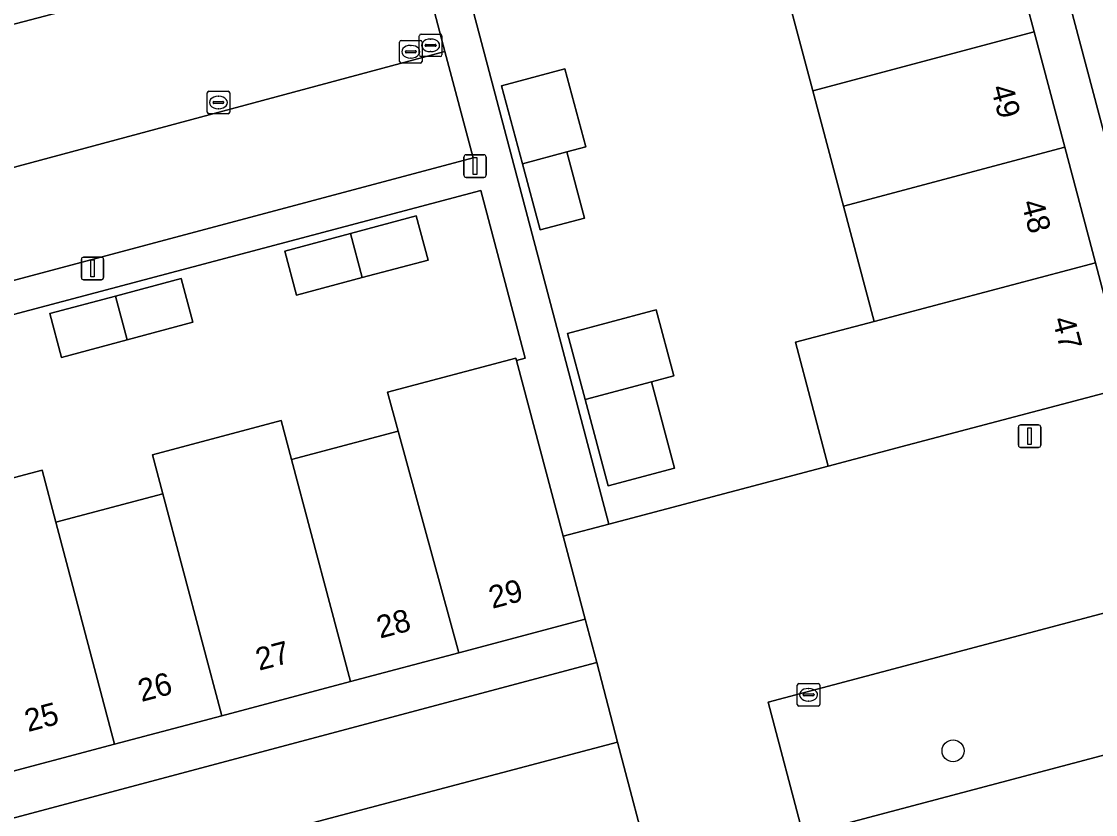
# Model space of a CAD drawing. Extents: x 162542 to 163147, y 380779 to 381521.
# Drawn here: x 162709.87 to 162757.53, y 381197.72 to 381232.91 of the extents above; entities that cross this region are included whole.
import ezdxf

# ---------------------------------------------------------------- set-up
doc = ezdxf.new("R2010")
doc.units = 0
for name, color, linetype in [('IMGEO_Boom', 7, 'Continuous'), ('IMGEO_Erf', 7, 'Continuous'), ('IMGEO_Groenvoorziening', 7, 'Continuous'), ('IMGEO_Kolk', 7, 'Continuous'), ('IMGEO_Lichtmast', 7, 'Continuous'), ('IMGEO_Pand', 7, 'Continuous'), ('IMGEO_Pand_nummerreeks', 7, 'Continuous'), ('IMGEO_Parkeervlak_open', 7, 'Continuous'), ('IMGEO_Rijbaan_lokaal_open', 7, 'Continuous'), ('IMGEO_Rioolput', 7, 'Continuous'), ('IMGEO_Voetpad_open', 7, 'Continuous')]:
    doc.layers.add(name, color=color, linetype=linetype)

msp = doc.modelspace()

# ---------------------------------------------------------------- linework, layer by layer
at = {"layer": 'IMGEO_Boom'}
msp.add_circle((162751.21, 381200.544), 0.489, dxfattribs=at)
at = {"layer": 'IMGEO_Erf'}
for points in [[(162744.149, 381279.784), (162742.367, 381279.309), (162743.667, 381274.41), (162743.797, 381273.921), (162742.727, 381273.637), (162743.189, 381271.897), (162744.259, 381272.181), (162745.094, 381269.035), (162746.512, 381263.696), (162747.763, 381258.981), (162749.288, 381253.236), (162750.533, 381248.547), (162751.429, 381245.173), (162750.365, 381244.868), (162750.827, 381243.126), (162751.891, 381243.431), (162751.943, 381243.235), (162752.106, 381242.624), (162753.452, 381237.55), (162754.805, 381232.452), (162756.164, 381227.332), (162757.525, 381222.201), (162758.984, 381216.704), (162760.777, 381217.178)], [(162733.985, 381230.811), (162734.91, 381227.345), (162734.066, 381227.12), (162734.849, 381224.188), (162732.878, 381223.662), (162732.095, 381226.594), (162731.17, 381230.06)], [(162721.556, 381222.72), (162724.468, 381223.499), (162727.387, 381224.28), (162727.911, 381222.324), (162724.992, 381221.543), (162722.072, 381220.761)], [(162711.121, 381219.944), (162714.034, 381220.723), (162716.95, 381221.503), (162717.469, 381219.561), (162714.552, 381218.783), (162711.635, 381218.004)], [(162737.855, 381220.069), (162738.035, 381220.117), (162738.819, 381217.18), (162737.828, 381216.916), (162738.845, 381213.083), (162735.907, 381212.3), (162734.886, 381216.132), (162734.103, 381219.069)]]:
    msp.add_lwpolyline(points, close=True, dxfattribs=at)
for points in [[(162721.568, 381264.953), (162735.925, 381210.607), (162745.669, 381213.183), (162744.216, 381218.679), (162747.704, 381219.602), (162746.343, 381224.72), (162744.981, 381229.839), (162743.62, 381234.957)], [(162705.078, 381211.488), (162710.779, 381213.004), (162711.391, 381210.689), (162716.137, 381211.949), (162715.678, 381213.677), (162721.392, 381215.196), (162721.852, 381213.468), (162726.586, 381214.725), (162726.113, 381216.459), (162731.811, 381217.971), (162731.839, 381217.865), (162732.225, 381217.967), (162730.249, 381225.411), (162696.73, 381216.515)], [(162690.946, 381195.54), (162687.929, 381198.743), (162687.849, 381198.668), (162687.41, 381199.136), (162687.487, 381199.208), (162684.47, 381202.415), (162684.391, 381202.339), (162683.889, 381202.869), (162682.507, 381201.562), (162690.949, 381192.615), (162735.396, 381204.465), (162734.886, 381206.386), (162729.268, 381204.894), (162724.473, 381203.621), (162718.757, 381202.103), (162713.994, 381200.841), (162708.31, 381199.334), (162703.321, 381198.012), (162703.349, 381197.905), (162703.116, 381197.844), (162702.845, 381197.772), (162702.817, 381197.878), (162702.689, 381197.844), (162699.57, 381197.013)]]:
    msp.add_lwpolyline(points, dxfattribs=at)
at = {"layer": 'IMGEO_Groenvoorziening'}
for points in [[(162725.799, 381242.395), (162724.166, 381248.556), (162706.988, 381232.279), (162707.019, 381232.142), (162707.144, 381232.175), (162717.44, 381234.879), (162717.359, 381235.188), (162716.135, 381239.802)], [(162763.302, 381208.084), (162743.002, 381202.706), (162744.562, 381196.817), (162764.861, 381202.201)], [(162736.313, 381200.934), (162717.693, 381196.001), (162719.198, 381190.095), (162737.873, 381195.045)]]:
    msp.add_lwpolyline(points, close=True, dxfattribs=at)
at = {"layer": 'IMGEO_Kolk'}
for p, q in [((162726.643, 381231.14), (162726.643, 381231.992)), ((162726.718, 381232.066), (162727.57, 381232.066)), ((162727.131, 381231.846), (162727.156, 381231.846)), ((162727.644, 381231.992), (162727.644, 381231.14)), ((162726.902, 381231.56), (162726.902, 381231.572)), ((162727.34, 381231.523), (162726.942, 381231.523)), ((162726.945, 381231.609), (162727.343, 381231.609)), ((162727.154, 381231.286), (162727.129, 381231.286)), ((162727.386, 381231.572), (162727.386, 381231.56)), ((162727.57, 381231.066), (162726.718, 381231.066)), ((162718.106, 381228.888), (162718.106, 381229.74)), ((162718.181, 381229.814), (162719.033, 381229.814)), ((162718.594, 381229.594), (162718.619, 381229.594)), ((162719.107, 381229.74), (162719.107, 381228.888)), ((162718.365, 381229.308), (162718.365, 381229.32)), ((162718.803, 381229.271), (162718.405, 381229.271)), ((162718.408, 381229.357), (162718.806, 381229.357)), ((162718.617, 381229.034), (162718.592, 381229.034)), ((162718.849, 381229.32), (162718.849, 381229.308)), ((162719.033, 381228.814), (162718.181, 381228.814))]:
    msp.add_line(p, q, dxfattribs=at)
for points in [[(162726.643, 381231.14), (162726.643, 381231.992)], [(162726.718, 381232.066), (162727.57, 381232.066)], [(162727.644, 381231.992), (162727.644, 381231.14)], [(162727.57, 381231.066), (162726.718, 381231.066)], [(162718.106, 381228.888), (162718.106, 381229.74)], [(162718.181, 381229.814), (162719.033, 381229.814)], [(162719.107, 381229.74), (162719.107, 381228.888)], [(162719.033, 381228.814), (162718.181, 381228.814)]]:
    msp.add_lwpolyline(points, dxfattribs=at)
for centre, radius, start, end in [((162726.72, 381231.99), 0.0765, 91.552, 178.448), ((162726.72, 381231.99), 0.0765, 91.552, 178.448), ((162727.568, 381231.99), 0.0765, 1.552, 88.448), ((162727.568, 381231.99), 0.0765, 1.552, 88.448), ((162726.942, 381231.569), 0.0403, 85.8775, 175.7526), ((162726.939, 381231.559), 0.0366, 178.938, 274.7102), ((162727.343, 381231.566), 0.043, 264.8664, 352.4533), ((162727.347, 381231.571), 0.0386, 1.7309, 96.639), ((162726.72, 381231.142), 0.0765, 181.552, 268.448), ((162726.72, 381231.142), 0.0765, 181.552, 268.448), ((162727.568, 381231.142), 0.0765, 271.552, 358.448), ((162727.568, 381231.142), 0.0765, 271.552, 358.448), ((162718.183, 381229.738), 0.0765, 91.552, 178.448), ((162718.183, 381229.738), 0.0765, 91.552, 178.448), ((162719.031, 381229.738), 0.0765, 1.552, 88.448), ((162719.031, 381229.738), 0.0765, 1.552, 88.448), ((162718.405, 381229.317), 0.0403, 85.8775, 175.7526), ((162718.402, 381229.307), 0.0366, 178.938, 274.7102), ((162718.806, 381229.314), 0.043, 264.8664, 352.4533), ((162718.81, 381229.319), 0.0386, 1.7309, 96.639), ((162718.183, 381228.89), 0.0765, 181.552, 268.448), ((162718.183, 381228.89), 0.0765, 181.552, 268.448), ((162719.031, 381228.89), 0.0765, 271.552, 358.448), ((162719.031, 381228.89), 0.0765, 271.552, 358.448)]:
    msp.add_arc(centre, radius, start, end, dxfattribs=at)
for centre, major_axis, ratio, start_param, end_param in [((162727.13, 381231.566), (-0.387, 0.002), 0.722429, 4.712389, 7.853982), ((162727.155, 381231.566), (-0.39, 0.002), 0.717154, 1.570796, 4.712389), ((162718.593, 381229.314), (-0.387, 0.002), 0.722429, 4.712389, 7.853982), ((162718.618, 381229.314), (-0.39, 0.002), 0.717154, 1.570796, 4.712389)]:
    msp.add_ellipse(centre, major_axis=major_axis, ratio=ratio, start_param=start_param, end_param=end_param, dxfattribs=at)
at = {"layer": 'IMGEO_Lichtmast'}
for p, q in [((162729.597, 381226.993), (162730.387, 381226.993)), ((162730.387, 381226.993), (162729.597, 381226.993)), ((162729.497, 381226.093), (162729.497, 381226.893)), ((162729.497, 381226.893), (162729.497, 381226.093)), ((162730.487, 381226.893), (162730.487, 381226.093)), ((162730.487, 381226.093), (162730.487, 381226.893)), ((162730.387, 381225.993), (162729.597, 381225.993)), ((162729.597, 381225.993), (162730.387, 381225.993)), ((162712.522, 381221.551), (162712.522, 381222.351)), ((162712.522, 381222.351), (162712.522, 381221.551)), ((162712.622, 381222.451), (162713.412, 381222.451)), ((162713.412, 381222.451), (162712.622, 381222.451)), ((162713.512, 381222.351), (162713.512, 381221.551)), ((162713.512, 381221.551), (162713.512, 381222.351)), ((162713.412, 381221.451), (162712.622, 381221.451)), ((162712.622, 381221.451), (162713.412, 381221.451)), ((162754.107, 381214.109), (162754.107, 381214.909)), ((162754.107, 381214.909), (162754.107, 381214.109)), ((162754.207, 381215.009), (162754.997, 381215.009)), ((162754.997, 381215.009), (162754.207, 381215.009)), ((162755.097, 381214.909), (162755.097, 381214.109)), ((162755.097, 381214.109), (162755.097, 381214.909)), ((162754.997, 381214.009), (162754.207, 381214.009)), ((162754.207, 381214.009), (162754.997, 381214.009))]:
    msp.add_line(p, q, dxfattribs=at)
for points in [[(162729.917, 381226.868), (162730.067, 381226.868), (162730.067, 381226.118), (162729.917, 381226.118), (162729.917, 381226.868)], [(162712.942, 381222.326), (162713.092, 381222.326), (162713.092, 381221.576), (162712.942, 381221.576), (162712.942, 381222.326)], [(162754.527, 381214.884), (162754.677, 381214.884), (162754.677, 381214.134), (162754.527, 381214.134), (162754.527, 381214.884)]]:
    msp.add_lwpolyline(points, dxfattribs=at)
for centre, start, end in [((162729.597, 381226.893), 90, 180), ((162729.597, 381226.893), 90, 180), ((162730.387, 381226.893), 0, 90), ((162730.387, 381226.893), 360, 90), ((162729.597, 381226.093), 180, 270), ((162729.597, 381226.093), 180, 270), ((162730.387, 381226.093), 270, 0), ((162730.387, 381226.093), 270, 0), ((162712.622, 381222.351), 90, 180), ((162712.622, 381222.351), 90, 180), ((162713.412, 381222.351), 0, 90), ((162713.412, 381222.351), 360, 90), ((162712.622, 381221.551), 180, 270), ((162712.622, 381221.551), 180, 270), ((162713.412, 381221.551), 270, 0), ((162713.412, 381221.551), 270, 0), ((162754.207, 381214.909), 90, 180), ((162754.207, 381214.909), 90, 180), ((162754.997, 381214.909), 0, 90), ((162754.997, 381214.909), 360, 90), ((162754.207, 381214.109), 180, 270), ((162754.207, 381214.109), 180, 270), ((162754.997, 381214.109), 270, 0), ((162754.997, 381214.109), 270, 0)]:
    msp.add_arc(centre, 0.1, start, end, dxfattribs=at)
at = {"layer": 'IMGEO_Pand'}
for points in [[(162753.452, 381237.55), (162743.62, 381234.957), (162744.981, 381229.839), (162754.805, 381232.452)], [(162754.805, 381232.452), (162744.981, 381229.839), (162746.343, 381224.72), (162756.164, 381227.332)], [(162733.985, 381230.811), (162731.17, 381230.06), (162732.095, 381226.594), (162734.066, 381227.12), (162734.91, 381227.345)], [(162734.066, 381227.12), (162732.095, 381226.594), (162732.878, 381223.662), (162734.849, 381224.188)], [(162757.525, 381222.201), (162756.164, 381227.332), (162746.343, 381224.72), (162747.704, 381219.602)], [(162727.387, 381224.28), (162724.468, 381223.499), (162724.992, 381221.543), (162727.911, 381222.324)], [(162724.468, 381223.499), (162721.556, 381222.72), (162722.072, 381220.761), (162724.992, 381221.543)], [(162757.525, 381222.201), (162747.704, 381219.602), (162744.216, 381218.679), (162745.669, 381213.183), (162749.165, 381214.108), (162758.984, 381216.704)], [(162716.95, 381221.503), (162714.034, 381220.723), (162714.552, 381218.783), (162717.469, 381219.561)], [(162714.034, 381220.723), (162711.121, 381219.944), (162711.635, 381218.004), (162714.552, 381218.783)], [(162738.035, 381220.117), (162737.855, 381220.069), (162734.103, 381219.069), (162734.886, 381216.132), (162737.828, 381216.916), (162738.819, 381217.18)], [(162731.839, 381217.865), (162731.811, 381217.971), (162726.113, 381216.459), (162726.586, 381214.725), (162729.268, 381204.894), (162734.886, 381206.386), (162733.907, 381210.073)], [(162737.828, 381216.916), (162734.886, 381216.132), (162735.907, 381212.3), (162738.845, 381213.083)], [(162721.852, 381213.468), (162721.392, 381215.196), (162715.678, 381213.677), (162716.137, 381211.949), (162718.757, 381202.103), (162724.473, 381203.621)], [(162726.586, 381214.725), (162721.852, 381213.468), (162724.473, 381203.621), (162729.268, 381204.894)], [(162711.391, 381210.689), (162710.779, 381213.004), (162705.078, 381211.488), (162705.693, 381209.175), (162708.31, 381199.334), (162713.994, 381200.841)], [(162716.137, 381211.949), (162711.391, 381210.689), (162713.994, 381200.841), (162718.757, 381202.103)]]:
    msp.add_lwpolyline(points, close=True, dxfattribs=at)
at = {"layer": 'IMGEO_Parkeervlak_open'}
msp.add_lwpolyline([(162728.656, 381231.579), (162699.849, 381223.847), (162701.06, 381219.172), (162729.91, 381226.858)], close=True, dxfattribs=at)
at = {"layer": 'IMGEO_Rijbaan_lokaal_open'}
msp.add_lwpolyline([(162728.656, 381231.579), (162727.036, 381237.729), (162717.359, 381235.188), (162717.44, 381234.879), (162707.144, 381232.175), (162707.019, 381232.142), (162703.666, 381231.209), (162700.747, 381230.44), (162700.456, 381230.763), (162700.677, 381230.974), (162688.475, 381243.889), (162691.953, 381247.17), (162691.301, 381247.857), (162679.601, 381236.83), (162680.253, 381236.137), (162683.764, 381239.482), (162697.438, 381224.879), (162697.666, 381225.113), (162698.805, 381223.893), (162699.779, 381224.12), (162699.849, 381223.847)], close=True, dxfattribs=at)
at = {"layer": 'IMGEO_Rioolput'}
for p, q in [((162727.522, 381231.424), (162727.522, 381232.276)), ((162727.597, 381232.35), (162728.449, 381232.35)), ((162728.523, 381232.276), (162728.523, 381231.424)), ((162727.781, 381231.844), (162727.781, 381231.856)), ((162728.219, 381231.807), (162727.821, 381231.807)), ((162727.824, 381231.893), (162728.222, 381231.893)), ((162728.01, 381232.13), (162728.035, 381232.13)), ((162728.265, 381231.856), (162728.265, 381231.844)), ((162728.449, 381231.35), (162727.597, 381231.35)), ((162728.033, 381231.57), (162728.008, 381231.57)), ((162744.296, 381202.605), (162744.296, 381203.457)), ((162744.371, 381203.531), (162745.223, 381203.531)), ((162744.784, 381203.311), (162744.809, 381203.311)), ((162745.297, 381203.457), (162745.297, 381202.605)), ((162744.555, 381203.025), (162744.555, 381203.037)), ((162744.993, 381202.988), (162744.595, 381202.988)), ((162744.598, 381203.074), (162744.996, 381203.074)), ((162744.807, 381202.751), (162744.782, 381202.751)), ((162745.039, 381203.037), (162745.039, 381203.025)), ((162745.223, 381202.531), (162744.371, 381202.531))]:
    msp.add_line(p, q, dxfattribs=at)
for points in [[(162727.522, 381231.424), (162727.522, 381232.276)], [(162727.597, 381232.35), (162728.449, 381232.35)], [(162728.523, 381232.276), (162728.523, 381231.424)], [(162728.449, 381231.35), (162727.597, 381231.35)], [(162744.296, 381202.605), (162744.296, 381203.457)], [(162744.371, 381203.531), (162745.223, 381203.531)], [(162745.297, 381203.457), (162745.297, 381202.605)], [(162745.223, 381202.531), (162744.371, 381202.531)]]:
    msp.add_lwpolyline(points, dxfattribs=at)
for centre, radius, start, end in [((162727.599, 381232.274), 0.0765, 91.552, 178.448), ((162727.599, 381232.274), 0.0765, 91.552, 178.448), ((162728.447, 381232.274), 0.0765, 1.552, 88.448), ((162728.447, 381232.274), 0.0765, 1.552, 88.448), ((162727.821, 381231.853), 0.0403, 85.8775, 175.7526), ((162727.818, 381231.843), 0.0366, 178.938, 274.7102), ((162728.222, 381231.85), 0.043, 264.8664, 352.4533), ((162728.226, 381231.855), 0.0386, 1.7309, 96.639), ((162727.599, 381231.426), 0.0765, 181.552, 268.448), ((162727.599, 381231.426), 0.0765, 181.552, 268.448), ((162728.447, 381231.426), 0.0765, 271.552, 358.448), ((162728.447, 381231.426), 0.0765, 271.552, 358.448), ((162744.373, 381203.455), 0.0765, 91.552, 178.448), ((162744.373, 381203.455), 0.0765, 91.552, 178.448), ((162745.221, 381203.455), 0.0765, 1.552, 88.448), ((162745.221, 381203.455), 0.0765, 1.552, 88.448), ((162744.595, 381203.034), 0.0403, 85.8775, 175.7526), ((162744.592, 381203.024), 0.0366, 178.938, 274.7102), ((162744.996, 381203.031), 0.043, 264.8664, 352.4533), ((162745, 381203.036), 0.0386, 1.7309, 96.639), ((162744.373, 381202.607), 0.0765, 181.552, 268.448), ((162744.373, 381202.607), 0.0765, 181.552, 268.448), ((162745.221, 381202.607), 0.0765, 271.552, 358.448), ((162745.221, 381202.607), 0.0765, 271.552, 358.448)]:
    msp.add_arc(centre, radius, start, end, dxfattribs=at)
for centre, major_axis, ratio, start_param, end_param in [((162728.009, 381231.85), (-0.387, 0.002), 0.722429, 4.712389, 7.853982), ((162728.034, 381231.85), (-0.39, 0.002), 0.717154, 1.570796, 4.712389), ((162744.783, 381203.031), (-0.387, 0.002), 0.722429, 4.712389, 7.853982), ((162744.808, 381203.031), (-0.39, 0.002), 0.717154, 1.570796, 4.712389)]:
    msp.add_ellipse(centre, major_axis=major_axis, ratio=ratio, start_param=start_param, end_param=end_param, dxfattribs=at)
at = {"layer": 'IMGEO_Voetpad_open'}
for points in [[(162757.59, 381310.24), (162739.401, 381293.119), (162740.695, 381292.754), (162744.149, 381279.784), (162760.777, 381217.178)], [(162678.254, 381235.563), (162682.331, 381231.223), (162682.628, 381231.503), (162696.73, 381216.515), (162730.249, 381225.411), (162732.225, 381217.967), (162731.839, 381217.865), (162733.907, 381210.073), (162735.925, 381210.607), (162721.568, 381264.953)], [(162727.036, 381237.729), (162728.656, 381231.579), (162729.91, 381226.858), (162701.06, 381219.172), (162697.175, 381218.132), (162693.896, 381221.629), (162680.253, 381236.137)], [(162758.984, 381216.704), (162749.165, 381214.108), (162745.669, 381213.183), (162735.925, 381210.607), (162733.907, 381210.073), (162734.886, 381206.386), (162735.396, 381204.465), (162736.313, 381200.934), (162737.873, 381195.045), (162739.9, 381195.582), (162744.562, 381196.817), (162743.002, 381202.706), (162763.302, 381208.084)], [(162670.936, 381177.305), (162672.612, 381177.749), (162671.064, 381183.564), (162697.537, 381190.645), (162699.108, 381184.771), (162700.785, 381185.215), (162699.246, 381191.087), (162716.019, 381195.533), (162717.541, 381189.656), (162719.198, 381190.095), (162717.693, 381196.001), (162736.313, 381200.934), (162735.396, 381204.465), (162690.949, 381192.615), (162688.758, 381192.072), (162678.158, 381189.24), (162654.703, 381182.974)]]:
    msp.add_lwpolyline(points, dxfattribs=at)
msp.add_lwpolyline([(162864.115, 381283.64), (162872.439, 381291.347), (162871.434, 381295.246), (162870.795, 381295.515), (162862.582, 381287.674), (162840.913, 381267.294), (162839.922, 381266.362), (162801.587, 381230.307), (162797.686, 381227.138), (162787.433, 381220.358), (162785.212, 381218.724), (162773.466, 381210.777), (162763.302, 381208.084), (162764.861, 381202.201), (162744.562, 381196.817), (162739.9, 381195.582), (162741.119, 381190.891), (162766.134, 381197.592), (162774.367, 381199.798), (162775.779, 381206.104), (162787.491, 381214.105), (162788.325, 381214.675), (162796.372, 381220.172), (162796.565, 381219.956)], close=True, dxfattribs=at)

# ---------------------------------------------------------------- texts
at = {"layer": 'IMGEO_Pand_nummerreeks'}
for s, rotation, p in [('49', 284.868, (162752.877, 381229.97)), ('48', 284.8566, (162754.23, 381224.87)), ('47', 284.8623, (162755.608, 381219.68)), ('29', 14.874, (162730.76, 381206.842)), ('28', 14.8683, (162725.78, 381205.52)), ('27', 14.874, (162720.412, 381204.095)), ('26', 14.8396, (162715.19, 381202.709)), ('25', 14.8511, (162710.157, 381201.375))]:
    msp.add_text(s, height=1, rotation=rotation, dxfattribs=at).set_placement(p)

doc.saveas('drawing.dxf')
